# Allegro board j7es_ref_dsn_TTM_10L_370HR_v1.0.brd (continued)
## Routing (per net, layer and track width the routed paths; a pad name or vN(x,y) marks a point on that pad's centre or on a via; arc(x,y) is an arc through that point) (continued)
N31196104: length 5.5
  TOP w0.203: R1031.1 181.47,57 180.74,57 180.59,57.14 C1053.1 179.07,57.14 178.69,56.76 177.55,56.76 177.31,56.99 U1008.16
N31196146: length 8.7
  TOP w0.203: C1069.1 v2(173.86,44.57) ; U1008.7 173.41,50.72 v2(173.23,50.54)
  BOTTOM w0.203: v2(173.23,50.54) 173.23,45.2 v2(173.86,44.57)
N31196169: length 10.1
  TOP w0.203: v2(171.44,43.92) 171.45,43.93 171.45,43.93 171.96,44.44 R1046.1 ; U1008.5 172.11,50.69 v2(171.89,50.47)
  BOTTOM w0.203: v2(171.89,50.47) 172.72,49.65 172.72,46.73 171.45,45.46 171.45,43.93 v2(171.44,43.92)
N31196187: length 10.3
  TOP w0.203: R1042.1 172.21,48.25 172.09,48.38 v2(172.09,48.88) 172.09,49.65 172.59,50.15 172.59,50.92 172.76,51.08 U1008.6 ; C1071.2 v2(170.94,44.44)
  BOTTOM w0.203: v2(170.94,44.44) 170.94,45.84 172.09,46.98 v2(172.09,48.88)
N31196205: length 10.4
  TOP w0.203: U1008.4 171.46,50.8 171.32,50.66 v2(171.32,49.9) ; R1040.1 168.02,45.84 v2(168.4,45.46) R1045.1
  BOTTOM w0.203: v2(171.32,49.9) 171.32,48.38 v2(168.4,45.46)
N31196259: length 4.4
  TOP w0.203: U1008.9 174.71,49.31 R1036.2 174.77,49.25 174.77,48.39 174.62,48.25 C1065.1
N31196266: length 1.5
  TOP w0.203: C1064.1 173.37,47.89 173.37,48.4 173.23,48.54 R1036.1
N31197066: length 9.1
  TOP w0.203: C1070.1 v2(175.58,44.57) ; U1008.8 v2(174.06,50.54)
  BOTTOM w0.203: v2(174.06,50.54) 174.06,46.08 v2(175.58,44.57)
N31197134: length 6.8
  TOP w0.203: U1008.3 v2(170.81,50.54) ; C1062.2 169.41,48.12 v2(169.41,49.14) R1037.2
  BOTTOM w0.203: v2(170.81,50.54) v2(169.41,49.14)
N31197473: length 3.5
  TOP w0.203: R1035.2 181.48,49.52 181.63,49.66 182.48,49.66 R1038.1 TP1012.1
N31206842: length 11.8
  TOP w0.305: 163.32,17.13 163.83,16.63 165.23,16.63 165.54,16.93 U1006.2 ; 163.32,17.13 Q1002.4 ; 163.32,17.13 163.32,18.91 165.23,20.82 165.72,20.82 166.19,21.29 U1006.6
N31206856: length 5.5
  TOP w0.305: U1006.1 164.89,19.28 165.16,19.55 C1029.1
N31206860: length 6
  TOP w0.305: U1006.7 165.54,23.78 166.01,24.25 168.02,24.25 169.04,23.23 C1029.2
N31206880: length 14.7
  BOTTOM w0.127: v2(157.23,21.96) 155.19,19.93 155.19,12.56 154.69,12.05 152.27,12.05 151.76,11.55 R1131.2
N31207095: length 2.1
  TOP w0.127: v2(151.76,9.13) 151.61,9.29 DS1000.2
  BOTTOM w0.127: v2(151.76,9.13) R1131.1
N31208453: length 2.7
  TOP w0.203: U1007.13 v2(190.63,99.43)
  BOTTOM w0.203: v2(190.63,99.43) 190.63,98.29 R1139.2
N31208462: length 2
  TOP w0.203: v2(191.39,98.54) 191.79,98.94 U1007.14
  BOTTOM w0.203: v2(191.39,98.54) 191.13,98.29 R1140.1
N31208471: length 2.9
  TOP w0.203: U1007.8 190.13,102.08 v2(189.48,102.73)
  BOTTOM w0.203: R1144.2 188.98,103.24 v2(189.48,102.73)
N31208480: length 1.8
  TOP w0.203: v2(190.12,103.24) 190.12,102.78 190.32,102.58 U1007.7
  BOTTOM w0.203: R1145.1 v2(190.12,103.24)
N31208503: length 13.8
  L2-SIGNAL w0.305: v2(188.21,105.02) 179.27,105.02 v2(178.09,103.84)
  BOTTOM w0.305: Q1008.4 v2(178.09,103.84) ; v2(188.21,105.02) 190.12,105.02
N31208524: length 7.6
  BOTTOM w0.305: R1140.2 R1139.1 189.41,96.64 189.1,96.94 189.1,97.78 186.73,100.15 Q1007.4
N31208551: length 15.6
  TOP w0.203: U1007.12 190.02,100.09 189.74,99.81 v2(189.74,99.3) 189.1,98.67 C1037.1 ; R1017.1 v2(193.29,93.84)
  L4-SIGNAL w0.203: v2(189.74,99.3) 191.13,97.91 191.13,96 v2(193.29,93.84)
  BOTTOM w0.203: v2(189.74,99.3) 186.18,102.86
  vias: v2(178.44,102.99) v2(178.44,102.22) v2(180.72,103.62) v2(180.72,102.86) v2(180.72,102.1) v2(181.61,103.62) v2(181.61,102.86) v2(181.61,102.1) v2(183.26,102.99) v2(183.26,102.1) v2(184.02,102.99) v2(184.02,102.1) v2(184.78,102.99) v2(184.78,102.1)
N31208672: length 3.8
  TOP w0.203: U1007.11 189.12,100.59 C1037.2 D1004.1
N31208960: length 1.4
  BOTTOM w0.508: C1204.1 R1152.1
N31209649: length 6.2
  TOP w0.203: R1017.2 R1018.1 C1033.2 195.2,97.78 193.78,99.2 U1007.18
N31209654: length 4.8
  TOP w0.203: U1007.17 193.28,98.94 194.18,98.03 C1033.1 R1022.1 R1018.2
N31222073: length 5.2
  TOP w0.203: U1007.23 194.89,102.08 195.2,102.39 v2(195.2,102.99) 195.96,103.75 C1047.2
  BOTTOM w0.203: v2(195.2,102.99) 195.83,103.62 R1143.1
  BOTTOM w0.254: R1142.1 v2(195.2,102.99)
N31222132: length 1.4
  TOP w0.203: R1026.1 196.47,101.34 C1039.2
N31222198: length 3.5
  TOP w0.203: C1038.1 197.61,100.19 R1026.2 195.45,100.19 195.06,100.59 U1007.20
N31222241: length 3.5
  TOP w0.203: C1050.2 195.96,104.89 194.44,103.37 U1007.24
N31222246: length 2.5
  TOP w0.203: C1041.2 195.96,102.61 194.94,101.58 U1007.22
N31222265: length 3.6
  TOP w0.203: U1007.6 191.29,103.6 190.44,104.45 190.44,104.83 189.99,105.27 188.98,105.27
N31222285: length 3.4
  TOP w0.203: 191.01,105.27 192.02,105.27 191.44,104.69 191.44,104.08 191.79,103.73 U1007.5
N31222303: length 2.1
  TOP w0.203: v2(192.15,104.26) 192.28,104.12 U1007.4
  BOTTOM w0.203: 192.15,105.27 v2(192.15,104.26)
N31222717: length 1.1
  TOP w0.203: R1024.2 R1023.1
N31223527: length 2.4
  BOTTOM w0.305: v2(184.28,124.58) 184.66,124.2 R1138.1 R1136.1
N31223584: length 3.9
  TOP w0.305: C1026.1 v2(184.66,118.99) 184.91,118.99 184.97,119.04 U1005.5
  BOTTOM w0.305: R1137.1 v2(184.66,118.99)
N31223889: length 1.3
  TOP w0.305: 183.39,123.56 C1025.2
N31224124: length 3.4
  TOP w0.127: U1005.9 191.96,116.26 v2(192.41,115.81)
  BOTTOM w0.127: 193.55,116.58 R1132.1 v2(192.41,115.81)
N31225374: length 4.3
  TOP w0.127: R1010.2 175.26,127.75 175.26,129.89 174.85,130.29 U1001.6
N31225630: length 3.6
  TOP w0.305: U1005.11 v2(193.25,118.39)
  BOTTOM w0.305: R1135.2 192.06,118.39 v2(193.25,118.39)
N31225660: length 4.5
  TOP w0.305: RJ1001.2 R1016.1 184.15,117.46 184.15,117.85 184.7,118.39 U1005.6
N31226612: length 6.8
  TOP w0.127: v2(184.72,117.53) 184.94,117.74 U1005.7
  TOP w0.305: U1005.4 v2(184.4,119.69) 183.95,119.24 C1027.2
  BOTTOM w0.127: v2(184.4,119.69) 184.02,119.31 184.02,118.23 v2(184.72,117.53)
N31313642: length 3.4
  TOP w0.127: U1001.8 176.02,132.2 176.28,131.94 176.28,131.56 176.91,130.93 R1007.2
N31313645: length 4.6
  TOP w0.127: R1008.2 177.93,130.67 176.66,131.94 176.66,132.45 176.41,132.7 U1001.9
N31555915: length 2.3
  BOTTOM w0.305: C1199.1 R1136.2 R1138.2
N33657189: length 9.9
  TOP w0.508: R2027.2 v2(27.56,45.07) 27.81,45.33 C2035.2 R2032.2 ; R2025.2 v2(27.56,39.87)
  BOTTOM w0.508: v2(27.56,39.87) v2(27.56,45.07)
N33657272: length 2.5
  TOP w0.112: L2006.1 32.35,43.11 31.85,42.61 31.29,42.61 C2030.2
N33657370: length 2.4
  TOP w0.112: L2006.2 32.32,41.71 31.78,42.26 31.22,42.26 C2029.2
N33657483: length 6.1
  TOP w0.127: Y2000.3 46.18,48.58 v2(46.1,48.5) 46.1,46.47 47.24,45.33 U2011.5
  BOTTOM w0.127: C2127.1 v2(46.1,48.5)
N33657512: length 3.6
  TOP w0.127: U2011.4 47.74,45.87 v2(48.09,46.22) 48.09,46.26 48.06,46.29 Y2000.1
  BOTTOM w0.127: C2126.1 48.13,46.26 v2(48.09,46.22)
N33657557: length 2.8
  TOP w0.127: v2(49.66,46.22) 48.75,45.31 U2011.2
  BOTTOM w0.127: R2115.2 v2(49.66,46.22)
N33658409: length 3.4
  TOP w0.127: 33.66,35.17 v2(33.66,33.77)
  BOTTOM w0.127: R2106.2 R2107.1 v2(33.66,33.77)
N33658469: length 3.4
  TOP w0.127: 33.66,29.58 v2(33.66,30.98)
  BOTTOM w0.127: R2099.2 R2100.2 v2(33.66,30.98)
N33658487: length 3
  TOP w0.127: 34.92,35.17 v2(34.92,33.77)
  BOTTOM w0.127: R2108.2 v2(34.92,33.77) R2105.2
N33658532: length 4
  TOP w0.127: U2007.14 v2(41.27,30.98)
  BOTTOM w0.127: v2(41.27,30.98) 41.66,31.36 R2102.2 R2103.2
N33658660: length 2.4
  TOP w0.127: 34.92,29.58 v2(34.92,28.18)
  BOTTOM w0.127: v2(34.92,28.18) R2101.1
N33658666: length 4.2
  BOTTOM w0.127: R2098.2 R2104.1 C2116.1
N33658711: length 2.4
  TOP w0.127: 37.46,35.17 v2(37.46,36.57)
  BOTTOM w0.127: v2(37.46,36.57) R2109.2
N33658728: length 2.4
  TOP w0.127: U2007.1 v2(41.27,36.57)
  BOTTOM w0.127: v2(41.27,36.57) R2110.2
N289339640: length 2.9
  TOP w0.305: 183.26,120.77 C1025.1 183.9,120.77 184.32,120.35 U1005.3

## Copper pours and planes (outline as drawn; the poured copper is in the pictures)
DGND on TOP: 70.61,105.02 70.61,103.37 69.72,102.48 65.53,102.48 65.53,104 68.07,104 69.09,105.02
DGND on TOP: 163.07,66.41 163.07,51.17 190.12,51.17 191.64,52.69 191.64,66.41 177.42,66.41 176.97,66.86 176.97,67.24 177.04,67.3 177.04,67.81 176.15,68.7 171.96,68.7 171.96,67.05 171.32,66.41 ; 1 cut-out
DGND on TOP: 123.06,95.75 125.6,95.75 125.6,99.05 123.06,99.05 123.06,99.56 119.89,99.56 119.89,95.24 123.06,95.24
DGND on TOP: 53.72,9.01 53.72,2.4 53.21,1.89 47.5,1.89 47.12,2.28 47.12,3.8 46.48,4.43 46.48,6.59 47.24,7.36 47.24,8.63 48.01,9.39 53.34,9.39
DGND on TOP: 178.82,47.23 178.44,47.61 177.67,47.61 177.29,47.23 169.16,47.23 168.91,46.98 168.91,46.47 169.55,45.84 169.8,45.84 169.8,45.33 170.05,45.07 175.9,45.07 176.91,44.06 181.74,44.06 181.74,46.47 180.97,47.23
DGND on TOP: 101.63,29.92 101.59,29.94 101.57,29.97 101.57,33.08 101.57,33.09 101.56,33.11 101.11,33.56 101.1,33.58 101.09,33.6 101.09,36.58 101.1,36.6 101.11,36.62 101.2,36.71 101.22,36.72 101.24,36.73 103.89,36.73 103.91,36.72 103.93,36.71 104.89,35.75 104.9,35.74 104.9,35.72 104.9,29.97 104.89,29.94 104.85,29.92
DGND on TOP: 37.08,9.01 37.08,2.4 36.58,1.89 30.86,1.89 30.48,2.28 30.48,3.8 29.84,4.43 29.84,6.59 30.61,7.36 30.61,8.63 31.37,9.39 36.7,9.39
DGND on TOP: 74.8,114.67 74.8,112.13 78.1,112.13 78.1,114.67 78.61,114.67 78.61,117.85 74.3,117.85 74.3,114.67
DGND on TOP: 78.1,98.16 78.1,100.7 74.8,100.7 74.8,98.16 74.3,98.16 74.3,94.99 78.61,94.99 78.61,98.16
DGND on TOP: 87,9.26 87,2.66 86.49,2.15 80.77,2.15 80.39,2.53 80.39,4.05 79.76,4.69 79.76,6.85 80.52,7.61 80.52,8.88 81.28,9.64 86.61,9.64
DGND on TOP: 70.36,9.13 70.36,2.53 69.85,2.02 64.13,2.02 63.75,2.4 63.75,3.93 63.12,4.56 63.12,6.72 63.88,7.48 63.88,8.75 64.64,9.51 69.98,9.51
DGND on TOP: 24.13,22.09 24.13,18.02 23.75,17.64 23.75,16.63 21.72,16.63 21.21,17.13 20.83,17.13 20.45,16.75 20.45,15.61 20.7,15.36 21.59,15.36 22.1,15.86 26.29,15.86 26.67,16.25 26.67,21.58 25.78,22.47 24.51,22.47
DGND on TOP: 132.72,91.56 134.37,91.56 135.25,90.67 135.25,86.48 133.73,86.48 133.73,89.02 132.72,90.03
DGND on TOP: 139.57,99.05 137.03,99.05 137.03,95.75 139.57,95.75 139.57,95.24 142.75,95.24 142.75,99.56 139.57,99.56
DGND on TOP: 202.69,152.26 202.69,1.39 0.63,1.39 0.63,152.26 ; 2 cut-outs
DGND on BOTTOM: 132.84,94.12 130.18,94.12 130.18,93.74 129.95,93.51 127.3,93.51 127.13,93.69 127.13,95.87 123.57,95.87 122.94,95.24 119.89,95.24 119.89,99.56 123.06,99.56 123.7,98.92 126.26,98.92 126.87,99.53 126.87,100.19 128.52,100.19 128.52,100.14 131.9,100.14 132.21,100.45 132.21,100.7 132.46,100.95 135,100.95 135.51,100.45 135.51,99.05 135.64,98.92 139.06,98.92 139.7,99.56 142.75,99.56 142.75,95.24 139.7,95.24 139.7,95.27 139.08,95.89 139.06,95.87 135.81,95.87 135.81,93.46 133.12,93.46 132.84,93.74
DGND on BOTTOM: 73.18,104.89 73.18,107.56 72.8,107.56 72.57,107.79 72.57,110.43 72.75,110.61 74.93,110.61 74.93,114.16 74.3,114.8 74.3,117.85 78.61,117.85 78.61,114.67 77.98,114.04 77.98,111.47 78.59,110.86 81.08,110.86 81.08,109.24 79.2,109.24 79.2,105.93 79.43,105.7 81.1,105.7 81.1,102.22 78.1,102.22 77.98,102.1 77.98,98.67 78.61,98.03 78.61,94.99 74.3,94.99 74.3,98.03 74.32,98.03 74.94,98.66 74.93,98.67 74.93,101.92 72.52,101.92 72.52,104.61 72.8,104.89
DGND on BOTTOM: 95,1.04 94.74,1.3 94.74,2.82 95.07,3.15 99.87,3.15 100.08,2.95 100.08,1.17 99.95,1.04
DGND on BOTTOM: 94.72,14.94 94.72,11.84 100.46,11.84 100.46,14.94
DGND on BOTTOM: 103.5,72 103.5,72.89 103.12,73.27 99.82,73.27 99.57,73.01 99.57,72.63 102.49,72.63 102.74,72.38 102.74,72 103,71.74 103.25,71.74
DGND on BOTTOM: 202.69,152.26 202.69,1.39 0.63,1.39 0.63,152.26 ; 2 cut-outs
DGND on BOTTOM: 124.87,16 126.59,16 126.96,15.63 126.96,13.59 127.22,13.33 127.22,9.78 126.58,9.14 124.93,9.14 124.42,9.65 124.42,15.56
DGND on L2-SIGNAL: 202.69,152.26 202.69,1.39 0.63,1.39 0.63,152.26 ; 2 cut-outs
DGND on L3-GND, L8-GND: 202.69,152.26 202.69,1.39 0.63,1.39 0.63,152.26
DGND on L4-SIGNAL: 202.69,152.26 202.69,1.39 0.63,1.39 0.63,152.26 ; 1 cut-out
DGND on L5-PWR/GND: 110.24,75.81 134.24,75.81 137.8,72.25 137.8,59.93 133.22,55.36 109.86,55.36 106.11,59.11 106.11,60.06 107.31,61.27 107.31,62.73 106.55,63.49 106.55,64.89 105.92,65.52 105.92,71.49
DGND on L7-SIGNAL: 202.69,152.26 202.69,1.39 0.63,1.39 0.63,152.26 ; 1 cut-out
DGND on L9-SIGNAL: 202.69,152.26 202.69,1.39 0.63,1.39 0.63,152.26 ; 3 cut-outs
V3V3_DP0 on TOP: 128.54,15.19 129.86,15.19 129.86,11.99 128.54,11.99
V3V3_DP0 on BOTTOM: 129.38,15.62 129.38,12.06 129.25,11.94 127.98,11.94 127.73,12.19 127.73,13.84 127.6,13.97 127.6,15.62 127.73,15.75 129.25,15.75
VBAT on TOP: 155.57,13.96 162.94,13.96 163.96,12.94 163.96,6.72 162.94,5.7 154.56,5.7 153.29,6.97 153.29,11.67
VBAT_A on TOP: 162.43,43.8 162.43,37.45 160.53,35.55 154.31,35.55 153.03,36.82 153.03,40.38 156.46,43.8
VBAT_A on L5-PWR/GND: 189.99,34.66 158.24,34.66 156.72,36.18 156.72,40.76 159.26,43.3 186.82,43.3 190.88,39.23 190.88,35.55
VBAT_F on TOP: 171.2,73.65 171.2,67.17 162.94,67.17 162.81,67.3 162.81,72.63 163.83,73.65
VBAT_F on TOP: 185.04,42.53 185.04,42.15 188.98,38.22 188.98,34.41 186.82,32.25 186.82,5.07 181.36,5.07 181.36,10.02 176.4,14.98 176.4,27.04 172.59,30.85 165.61,30.85 162.81,33.64 162.81,48.25 163.96,49.39 166.12,49.39 166.62,48.88 166.62,44.57 168.66,42.53
VBAT_PM on TOP: 162.69,18.4 163.7,17.39 165.48,17.39 166.5,18.4 169.04,18.4 169.04,15.86 167.77,14.59 155.32,14.59 153.42,12.69 149.22,12.69 148.59,13.32 148.59,18.4
VBAT_PM on BOTTOM: 154.43,17.01 148.72,17.01 148.72,31.74 149.86,32.88 191.13,32.88 197.23,38.98 197.23,66.66 196.98,66.92 192.91,66.92 191.9,65.9 191.9,48 185.93,42.03 149.22,42.03 143.89,36.69 143.89,16.37 147.7,12.56 154.18,12.56 154.43,12.82
VBAT_SYS on TOP: 175.51,98.41 175.51,94.99 182.25,88.25 185.55,88.25 186.82,86.98 186.82,83.81 186.88,83.75 186.88,82.92 192.91,82.92 195.07,85.08 195.07,91.94 193.04,93.97 193.04,99.3 192.53,99.81 192.15,99.81 192.15,98.8 190.75,97.4 190.75,96 190.12,95.37 188.85,95.37 185.8,98.41 185.8,99.18 185.42,99.56 183.39,99.56 182.25,98.41
VBAT_SYS on BOTTOM: 183.01,99.43 186.31,99.43 188.47,97.27 188.47,96.38 188.72,96.13 191.26,96.13 191.64,96.51 191.64,98.92 196.09,98.92 196.98,99.81 196.98,100.7 195.96,101.72 195.96,102.48 196.22,102.73 199.77,102.73 200.28,102.22 200.28,95.62 194.94,90.29 180.59,90.29 180.59,97.02
VBAT_SYS on BOTTOM: 187.71,86.48 193.04,86.48 194.94,84.57 194.94,80.51 194.06,79.62 187.58,79.62 186.56,80.63 186.56,85.33
VBUS_USBC_CONN on TOP: 173.1,133.47 172.09,133.47 172.09,133.59 171.32,133.59 170.24,134.67 170.24,141.21 172.59,141.21 172.59,135.88 173.1,135.37
VBUS_USBC_CONN on L2-SIGNAL: 186.56,145.28 186.56,138.42 178.31,130.16 147.19,130.16 146.94,130.42 146.94,135.12 157.73,145.91 185.93,145.91
VCC_12V0 on TOP: 97.28,31.14 97.28,36.91 97.49,37.11 100.33,37.11 100.71,36.73 100.71,33.27 101.12,32.87 101.12,30.94 101.04,30.86 99.57,30.86 99.29,31.14
VCC_12V_DSI0 on TOP: 100.54,26.83 100.54,25.07 99.98,24.51 99.98,23.53 102.31,21.19 102.31,4.55 101.17,3.41 96.77,3.41 95.13,5.05 95.13,20.18 96.77,21.82 96.77,24.93 97.26,25.42 97.26,27.16 97.35,27.25 100.12,27.25
VCC_12V_DSI0 on BOTTOM: 96.01,8.03 101.35,8.03 102.62,6.76 106.68,6.76 106.93,6.5 106.93,4.34 106.35,3.76 96.34,3.76 95.76,4.34 95.76,7.77
VCCA_3V3 on TOP: 153.8,108.57 157.73,104.64 157.73,97.91 153.54,93.72 135.64,93.72 135.25,94.1 135.25,100.45 133.1,102.61 133.1,107.69 133.99,108.57
VCCA_3V3 on TOP: 123.95,99.43 127.51,99.43 127.63,99.56 127.63,99.81 126.62,99.81 125.73,100.7 123.95,100.7
VCCA_3V3 on TOP: 138.68,95.37 135.13,95.37 135,95.24 135,94.99 136.02,94.99 136.91,94.1 138.68,94.1
VCCA_3V3 on TOP: 78.49,99.05 78.49,102.61 78.61,102.73 78.87,102.73 78.87,101.72 79.76,100.83 79.76,99.05
VCCA_3V3 on TOP: 71.5,106.29 72.85,106.29 72.85,106.8 69.22,106.8 69.22,105.78 70.99,105.78
VCCA_3V3 on TOP: 74.42,99.05 74.42,102.61 74.3,102.73 74.04,102.73 74.04,101.72 73.15,100.83 73.15,99.05
VCCA_3V3 on TOP: 74.42,113.78 74.42,110.23 74.3,110.1 74.04,110.1 74.04,111.11 73.15,112 73.15,113.78
VCCA_3V3 on TOP: 138.68,99.43 135.13,99.43 135,99.56 135,99.81 136.02,99.81 136.91,100.7 138.68,100.7
VCCA_3V3 on TOP: 123.95,95.37 127.51,95.37 127.63,95.24 127.63,94.99 126.62,94.99 125.73,94.1 123.95,94.1
VCCA_3V3 on TOP: 131.24,93.79 130.94,93.79 130.94,90.16 131.95,90.16 131.95,91.68 131.32,92.32 131.32,93.72
VCCA_3V3 on TOP: 78.49,113.78 78.49,110.23 78.61,110.1 78.87,110.1 78.87,111.11 79.76,112 79.76,113.78
VCCA_3V3 on BOTTOM: 128.4,101.32 128.43,101.34 129.01,101.34 129.03,101.34 129.05,101.35 129.41,101.72 129.44,101.73 129.46,101.73 129.95,102.07 129.53,102.48 129.5,102.48 129.43,102.54 129.42,102.56 129.41,102.58 129.41,103.44 129.43,103.48 129.46,103.49 129.61,103.49 129.67,103.48 129.72,103.48 131.03,103.48 131.08,103.48 131.14,103.49 132.06,103.49 132.08,103.49 132.09,103.48 132.32,103.26 132.34,103.24 132.36,103.24 133.46,103.24 133.48,103.24 133.49,103.23 133.57,103.15 133.58,103.13 133.58,103.1 133.55,103 133.53,102.98 133.52,102.98 133.24,102.5 133.72,102.24 133.74,102.25 133.76,102.24 133.84,102.19 133.85,102.17 133.86,102.15 133.86,101.39 133.84,101.35 133.81,101.34 132.32,101.34 132.3,101.33 132.29,101.32 131.84,100.87 131.83,100.86 131.83,100.84 131.83,100.63 131.82,100.61 131.81,100.59 131.76,100.54 131.74,100.53 131.72,100.52 128.96,100.52 128.92,100.54 128.91,100.57 128.44,100.57 128.4,100.59 128.38,100.63 128.38,101.24
VCCA_3V3 on BOTTOM: 78.71,113.81 80.24,113.81 80.24,119.12 70.48,119.12 70.1,118.73 70.1,116.58 72.77,113.91 74.68,113.91 74.68,111.11 74.55,110.99 72.64,110.99 72.39,110.73 72.39,107.69 72.77,107.3 72.77,105.65 72.14,105.02 72.14,101.72 74.42,101.72 74.8,101.34 74.8,98.92 74.42,98.54 66.42,98.54 65.15,99.81 65.28,99.94 65.28,102.99 64.01,102.99 63.88,102.86 63.88,102.99 61.59,102.99 60.2,104.38 60.2,107.05 61.47,108.32 66.17,108.32 66.67,108.83 66.67,113.78 64.52,115.94 64.52,122.67 88.14,122.67 90.2,120.61 90.2,111.93 90.17,111.93 90.17,106.42 87.5,103.75 87.5,100.27 85.83,98.59 78.71,98.59
VCCA_3V3 on L5-PWR/GND: 157.48,97.65 157.48,103.11 155.32,105.27 152.4,105.27 150.11,107.56 128.02,107.56 123.06,102.61 123.06,92.57 125.86,89.78 135,89.78 141.35,96.13 155.96,96.13
VCCA_3V3 on L6-PWR/GND: 85.14,118.79 157.35,118.79 160.53,115.61 160.53,101.97 157.35,98.8 149.33,98.8 149.33,105.55 149.35,105.58 149.35,106.16 148.34,107.18 114.55,107.18 110.97,103.6 91.16,103.6 90.3,102.73 90.3,98.92 73.28,98.92 72.45,99.75 72.45,105.34 69.85,107.94 69.85,113.15 71.12,114.42 79.38,114.42 79.88,113.91 79.88,109.08 80.26,108.7 82.42,108.7 82.8,109.08 82.8,116.45
VCCA_3V3 on L7-SIGNAL: 63.75,118.73 63.75,98.08 88.37,98.08 88.37,98.16 89.28,99.08 89.28,107.91 88.37,108.83 88.37,109.72 89.51,110.86 89.51,118.73
VDD1_LPDDR4_1V8 on BOTTOM: 121.82,55.87 119.63,58.06 119.63,75.15 121.44,76.95 121.44,84.95 118.62,87.77 118.62,89.14 117.47,90.29 115.95,90.29 114.55,91.68 114.55,105.27 116.71,107.43 128.02,107.43 129.16,106.29 129.16,101.84 128.91,101.59 128.4,101.59 127,102.99 119,102.99 117.47,101.46 117.47,93.46 119.13,91.81 124.21,91.81 131.06,84.95 131.06,79.87 135.76,75.17 135.76,57.54 134.09,55.87 ; 4 cut-outs
VDD1_LPDDR4_1V8 on L9-SIGNAL: 130.69,68.24 130.69,64.68 129.21,63.21 129.21,62.01 126.67,62.01 126.04,62.65 121.71,62.65 120.32,61.26 120.32,56.62 120.54,56.4 134.49,56.4 135.51,57.42 135.51,76.57 121.5,76.57 120.58,75.65 120.58,71.24 121.68,70.14 127.05,70.14 128.96,68.24 ; 1 cut-out
VDD18_DSI on TOP: 116.97,33.55 116.97,35.47 116.5,35.93 112.3,35.93 111.27,34.91 111.27,33.95 111.67,33.55
VDD18_DSI on L2-SIGNAL: 115.32,35.93 117.35,33.9 117.35,17.52 114.68,14.85 104.27,14.85 103.63,15.48 103.63,16.37 104.65,17.39 112.52,17.39 114.81,19.67 114.81,28.95 114.17,29.58 112.78,29.58 112.27,29.07 110.87,29.07 110.49,29.45 110.49,34.15 112.27,35.93
VDD_CORE_0V8 on TOP: 77.23,74.56 76.7,75.09 74.9,75.09 73.28,76.71 73.28,81.14 59.44,94.99 59.44,114.8 64.52,119.88 86.23,119.88 97.54,108.57 97.54,97.53 98.68,96.38 103.63,96.38 104.14,95.87 104.14,93.97 103.25,93.08 101.73,93.08 101.41,92.76 101.41,91.49 99.69,89.78 99.69,84.06 99.39,83.76 87,83.76 86.55,83.31 86.55,74.35 87.72,73.19 94.91,73.19 96.52,74.79 97.03,74.79 98.77,73.05 98.84,73.05 98.93,73.14 98.93,73.4 97.92,74.41 97.92,74.67 98.17,74.92 98.81,74.92 98.81,75.43 98.93,75.55 99.57,75.55 99.57,73.14 100.08,72.63 100.08,70.91 100.84,70.91 100.84,67.08 94.81,67.08 94.81,72.8 87.11,72.8 85.47,71.16 80.62,71.16 80.62,73.78 80.52,73.78 80.26,74.03 80.26,74.43 80.14,74.56
VDD_CORE_0V8 on BOTTOM: 71.12,120.34 71.13,120.37 71.17,120.39 81.74,120.39 81.77,120.37 81.79,120.34 81.79,114.85 81.77,114.81 81.74,114.8 79.93,114.8 79.9,114.81 79.88,114.85 79.88,117.7 79.88,117.72 79.87,117.73 79.39,118.21 79.37,118.22 79.35,118.23 73.55,118.23 73.53,118.22 73.52,118.21 73.04,117.73 73.03,117.72 73.03,117.7 73.03,114.85 73.01,114.81 72.97,114.8 71.17,114.8 71.13,114.81 71.12,114.85
VDD_CORE_0V8 on BOTTOM: 81.79,98.03 81.79,92.45 71.12,92.45 71.12,98.03 73.03,98.03 73.03,95.11 73.53,94.6 79.38,94.6 79.88,95.11 79.88,98.03
VDD_CORE_0V8 on BOTTOM: 93.6,96 94.11,96 94.23,96.13 94.23,97.78 94.11,97.91 93.98,97.91 93.97,97.89 93.71,97.89 93.68,97.93 92.2,97.93 92.2,96.64 92.46,96.38 93.22,96.38
VDD_CORE_0V8 on L2-SIGNAL: 103.76,72.38 107.08,72.38 107.08,65.24 97.16,65.24 96.49,65.9 94.36,65.9 94.11,66.16 94.11,70.6 93.6,71.11 84.45,71.11 83.69,71.87 80.39,71.87 75.62,76.65 75.62,79.31 60.71,94.22 60.71,118.99 88.01,118.99 99.69,107.3 99.69,72.76 100.84,71.62 100.84,68.7 102.87,68.7 103.76,69.59
VDD_CORE_0V8 on L4-SIGNAL: 87.25,91.46 87.25,93.33 83.95,96.64 66.8,96.64 65.28,95.11 65.28,92.7 66.52,91.46
VDD_CORE_0V8 on L6-PWR/GND: 90.04,80.25 75.95,80.25 75.95,82.03 73.28,84.7 73.28,98.67 90.04,98.67
VDD_CORE_0V8 on L9-SIGNAL: 94.11,42.79 95.38,41.52 107.7,41.52 108.2,42.03 108.2,42.92 106.81,44.31 106.43,44.31 100.2,50.54 100.2,59.3 99.82,59.68 99.82,69.2 99.95,69.33 99.95,72.38 100.71,73.14 100.71,76.06 99.06,77.71 94.23,77.71 93.47,76.95 93.47,74.67 93.85,74.28 94.36,74.28 94.87,74.79 95.12,74.79 95.25,74.67 95.25,73.52 93.47,71.74 93.47,66.92 95.12,65.27 95.12,64.12 95.88,63.36 95.88,58.92 96.27,58.54 96.27,51.42 94.11,49.27
VDD_CORE_0V8_REG_SW1 on TOP: 73.86,110.78 73.86,110.1 73.03,110.1 73.03,110.23 71.37,111.88 71.37,114.16 72.52,114.16 72.52,112.13
VDD_CORE_0V8_REG_SW2 on TOP: 79.04,110.78 79.04,110.1 79.88,110.1 79.88,110.23 81.53,111.88 81.53,114.16 80.39,114.16 80.39,112.13
VDD_CORE_0V8_REG_SW3 on TOP: 73.86,102.05 73.86,102.73 73.03,102.73 73.03,102.61 71.37,100.95 71.37,98.67 72.52,98.67 72.52,100.7
VDD_CORE_0V8_REG_SW4 on TOP: 79.04,102.05 79.04,102.73 79.88,102.73 79.88,102.61 81.53,100.95 81.53,98.67 80.39,98.67 80.39,100.7
VDD_CORE_RAM_0V85 on BOTTOM: 75.44,79.39 75.44,78.88 75.4,78.84 72.01,78.84 72.01,77.1 77.47,77.1 77.47,80 76.05,80
VDD_CORE_RAM_0V85 on L6-PWR/GND: 98.87,67.7 97.71,68.86 97.71,71.41 97.64,71.49 84.84,71.49 82.03,74.3 78.48,74.3 76.71,76.06 76.71,79.2 77.47,79.96 90.57,79.96 90.75,79.77 90.75,75.1 92.46,73.4 94.87,73.4 94.87,75.43 95.38,75.43 95.72,75.09 100.5,75.09 101.19,74.39 101.19,73.15 102.04,73.15 102.04,67.7
VDD_CPU_AVS on TOP: 99.69,83.68 99.69,73.27 99.77,73.2 99.77,71.62 101.22,71.62 101.22,69.33 103.45,69.33 103.45,72.76 107.57,72.76 107.57,75.94 108.58,76.95 112.78,76.95 112.83,76.9 120.32,76.9 123.19,79.77 123.19,81.5 128.14,81.5 128.14,83.17 125.73,85.59 125.73,104.76 124.97,105.53 118.11,105.53 117.09,104.51 117.09,94.35 114.81,92.06 103,92.06 99.95,89.02 99.95,83.94
VDD_CPU_AVS on BOTTOM: 119.51,94.5 119.51,94.48 119.52,94.46 120,93.98 120.02,93.97 120.04,93.97 122.89,93.97 122.92,93.95 122.94,93.92 122.94,92.12 122.92,92.08 122.89,92.06 119.25,92.06 117.73,93.59 117.73,101.34 119.13,102.73 122.89,102.73 122.92,102.72 122.94,102.68 122.94,100.88 122.92,100.84 122.89,100.83 120.29,100.83 120.27,100.82 120.25,100.81 119.52,100.08 119.51,100.06 119.51,100.04
VDD_CPU_AVS on L2-SIGNAL: 102.74,68.95 103.5,69.71 103.5,72.38 103.76,72.63 107.01,72.63 110.92,76.55 120.65,76.55 123.57,79.47 128.02,79.47 128.02,100.19 126.24,101.97 125.98,101.97 123.19,104.76 118.24,104.76 116.84,103.37 116.84,99.2 106.15,88.51 99.95,88.51 99.96,88.5 99.96,72.65 100.99,71.62 100.99,68.95
VDD_CPU_AVS_REG_SW1 on TOP: 126.95,94.81 127.63,94.81 127.63,93.97 127.51,93.97 125.86,92.32 123.57,92.32 123.57,93.46 125.6,93.46
VDD_CPU_AVS_REG_SW2 on TOP: 126.95,99.99 127.63,99.99 127.63,100.83 127.51,100.83 125.86,102.48 123.57,102.48 123.57,101.34 125.6,101.34
VDD_CPU_RAM_0V85 on BOTTOM: 90.17,104.48 91.32,104.48 91.37,104.43 91.37,101.26 91.31,101.21 91.9,101.21 92.96,100.14 92.96,99.56 92.46,99.05 90.17,99.05
VDD_CPU_RAM_0V85 on L5-PWR/GND: 102.58,67.83 101.32,67.83 99.95,69.2 99.95,73.01 100.97,74.03 100.97,75.3 101.23,75.57 102.25,75.57 102.49,75.81 102.49,76.82 101.98,77.33 101.73,77.33 101.73,78.35 101.6,78.48 101.6,84.7 101.85,84.95 101.85,88.38 93.85,96.38 92.84,96.38 91.82,97.4 91.82,99.81 93.22,101.21 96.52,101.21 105.79,91.94 105.79,85.33 104.01,83.56 104.01,82.56 104.41,82.16 104.41,79.73 106.93,77.21 106.93,74.79 105.54,73.4 105.54,70.79
VDD_DDR_1V1 on TOP: 137.1,78.66 127.16,78.66 126.71,79.11 123.32,79.11 120.65,76.44 110.74,76.44 108.84,74.54 108.84,60.19 106.43,60.19 106.43,57.39 112.27,51.55 134.35,51.55 140.84,58.04 140.84,74.92 ; 15 cut-outs
VDD_DDR_1V1 on TOP: 141.08,104.89 141.1,104.89 141.11,104.88 142.73,103.26 142.74,103.24 142.75,103.22 142.75,101.13 142.73,101.1 142.7,101.08 139.5,101.08 139.46,101.1 139.45,101.13 139.45,102.84 139.44,102.86 139.43,102.87 138.95,103.35 138.94,103.36 138.92,103.37 136.7,103.37 136.67,103.38 136.65,103.42 136.65,104.84 136.67,104.88 136.7,104.89
VDD_DDR_1V1 on L2-SIGNAL: outline of 101 points within 137.67,68.95 145.29,103.75
VDD_DDR_1V1 on L6-PWR/GND: 103.09,66.53 103.25,66.38 103.34,66.47 103.34,73.07 105.49,73.07 106.06,73.64 110.05,73.64 110.26,73.42 118.9,73.42 120.27,74.79 120.27,90.85 121.23,91.81 121.28,91.81 121.41,91.94 121.41,100.32 122.36,101.27 132.91,101.27 134.56,102.92 142.81,102.92 143.13,102.61 143.13,94.25 139.73,94.25 138.54,93.07 138.54,90.66 137.92,90.03 137.92,79.62 140.59,76.95 140.59,60.44 134.24,54.09 123.57,54.09 121.22,51.74 105.79,51.74 103.11,54.42 103.11,56.87 103.09,56.89
VDD_DDR_1V1 on L7-SIGNAL: 137.51,71.22 137.51,59.85 133.19,55.54 120.37,55.54 119.63,56.28 119.63,74.79 121.16,76.32 132.41,76.32
VDD_DDR_1V1_REG_SW on TOP: 135.69,99.99 135,99.99 135,100.83 135.13,100.83 136.78,102.48 139.06,102.48 139.06,101.34 137.03,101.34
VDD_IO_1V8 on TOP: 117.47,34.82 117.47,33.55 120.65,33.55 120.65,34.82
VDD_IO_1V8 on L2-SIGNAL: 116.4,99.37 105.92,88.89 101.98,88.89 101.73,89.14 101.73,98.67 118.36,115.31 155.96,115.31 162.43,108.83 162.43,84.32 151.76,73.65 151.76,18.15 146.18,12.56 123.32,12.56 117.98,17.9 117.98,34.03 119.38,35.42 120.4,35.42 125.48,30.34 125.48,25.9 126.62,24.75 139.19,24.75 145.92,31.49 145.92,102.1 143.89,104.13 124.33,104.13 123.32,105.15 117.98,105.15 116.4,103.56
VDD_IO_1V8 on L5-PWR/GND: 80.39,107.81 99.31,107.81 99.38,107.75 102.43,107.75 110.62,99.56 110.62,95.75 108.84,93.97 104.52,93.97 96.9,101.59 81.53,101.59 80.39,102.73
VDD_IO_1V8 on L6-PWR/GND: 105.16,75.94 104.37,76.72 104.37,77.82 106.55,80 106.55,87.14 101.96,87.14 101.04,88.05 101.04,92.24 101.09,92.24 101.09,103.11 111.25,103.11 111.25,94.22 111.63,93.84 114.73,93.84 116.33,92.24 116.33,75.94
VDD_IO_3V3 on TOP: outline of 82 points within 98.55,96.64 117.47,117.97
VDD_IO_3V3 on TOP: 150.88,108.07 150.88,109.21 151.51,109.84 155.83,109.84 156.08,109.59 156.97,109.59 156.97,108.07
VDD_IO_3V3 on BOTTOM: 97.92,15.9 97.92,18.19 95.63,18.19 95.63,15.9
VDD_IO_3V3 on L5-PWR/GND: 202.69,152.26 202.69,1.39 0.63,1.39 0.63,152.26 ; 1 cut-out
VDD_IO_3V3 on L6-PWR/GND: 100.61,92.65 100.61,87.37 101.37,86.6 106.68,86.6 106.68,84.06 106.3,83.68 106.3,80.13 104.19,78.02 104.19,74.77 105.66,74.77 105.66,73.54 105.39,73.27 101.51,73.27 101.51,74.37 100.71,75.17 96.52,75.17 96.01,75.68 94.49,75.68 94.49,73.65 92.58,73.65 91.19,75.05 90.75,75.56 90.75,80.47 90.35,80.87 90.35,90.34 90.36,90.35 90.36,102.42 90.93,102.99 100.46,102.99 100.69,102.76 100.69,92.73
VDD_MCU_0V85 on TOP: 85.85,42.92 87,41.77 88.52,41.77 88.9,42.15 88.9,45.96 90.81,47.87 90.81,49.65 90.42,50.03 90.04,50.03 89.79,49.77 89.41,49.77 89.41,55.36 89.28,55.49 87.5,55.49 87.5,49.9 87.38,49.77 86.36,49.77 85.85,49.27
VDD_MCU_0V85 on TOP: 142.6,93.46 142.65,93.43 142.64,93.38 142.59,93.27 142.57,93.16 142.57,91.87 142.61,91.7 142.74,91.55 142.75,91.53 142.75,91.1 142.73,91.06 142.7,91.05 140.86,91.05 140.84,91.04 140.83,91.03 139.71,89.92 139.7,89.91 139.67,89.91 139.53,90.09 139.31,90.16 136.92,90.16 136.88,90.18 136.87,90.22 136.87,91.38 136.88,91.41 136.92,91.43 138.92,91.43 138.94,91.43 138.95,91.44 139.69,92.18 139.7,92.19 139.7,92.21 139.7,93.41 139.71,93.45 139.75,93.46
VDD_MCU_0V85 on L4-SIGNAL: 95.63,67.17 94.11,67.17 92.46,65.52 92.46,51.55 89.92,49.01 86.49,49.01 85.98,49.52 85.98,55.87 89.28,59.17 89.28,66.66 90.81,68.19 90.93,68.19 90.93,70.73 91.44,71.24 94.11,71.24 94.23,71.36 95.63,71.36
VDD_MCU_0V85 on L6-PWR/GND: 85.75,57.75 85.74,57.72 85.74,59.19 93.73,67.17 93.73,67.55 93.22,68.06 93.22,69.74 94.49,71.01 95.17,71.01 95.17,70.58 95.43,70.58 95.68,70.83 96.75,70.83 96.9,70.68 96.9,68.67 97.59,67.99 97.59,64.94 97.61,64.91 97.59,64.89 97.59,48.33 100.33,45.58 102.49,45.58 103.89,46.98 103.89,49.14 105.66,50.92 121.41,50.92 123.83,53.33 134.75,53.33 141.73,60.31 141.73,77.08 138.68,80.13 138.68,89.7 140.13,91.15 140.13,91.61 139.29,92.45 139.29,93.33 139.8,93.84 145.57,93.84 148.87,90.54 151.64,90.54 153.67,88.51 153.67,61.71 136.78,44.82 122.05,44.82 120.9,43.68 120.9,38.72 119.89,37.71 92.33,37.71 85.75,44.29
VDD_MCU_0V85_REG_SW on TOP: 135.69,94.81 135,94.81 135,93.97 135.13,93.97 136.78,92.32 139.06,92.32 139.06,93.46 137.03,93.46
VDD_MCU_RAM_0V85 on L5-PWR/GND: 99.69,73.27 99.69,64.76 95.5,60.57 95.5,51.55 90.81,46.85 88.39,46.85 88.01,47.23 88.01,49.01 90.3,51.3 90.3,55.87 93.34,58.92 93.34,63.36 91.82,64.89 91.82,72.13 93.09,73.4 99.57,73.4
VDD_MCUIO_1V8 on L4-SIGNAL: 94.87,66.92 95.38,66.41 95.38,65.65 94.78,65.05 94.78,64.72 94.74,64.68 94.74,58.09 95.98,56.85 95.98,49.23 94.49,47.74 94.49,46.73 91.31,43.55 91.31,41.77 92.84,40.25 140.84,40.25 144.02,43.42 144.02,89.14 140.08,93.08 140.08,99.18 136.27,102.99 130.94,102.99 130.68,102.73 130.68,102.1 130.3,101.72 128.78,101.72 128.27,102.22 128.27,107.43 129.54,108.7 145.03,108.7 146.81,106.92 146.81,99.18 153.23,92.76 153.23,42.85 145.8,35.42 74.42,35.42 68.26,41.58 68.26,47.42 69.09,48.25 75.44,48.25 77.6,50.41 81.79,50.41 85.98,46.22 89.53,46.22 90.17,46.85 90.17,48.63 92.84,51.3 92.84,65.52 94.23,66.92
VDD_MCUIO_3V3 on BOTTOM: 59.94,96.76 59.31,97.4 59.31,100.32 61.21,100.32 62.61,101.72 63.5,101.72 63.5,100.45 62.1,99.05 62.1,96.76
VDD_MCUIO_3V3 on L4-SIGNAL: 77.34,103.24 77.34,99.3 76.33,98.29 57.66,98.29 57.28,98.67 57.28,101.59 59.31,103.62 76.96,103.62
VDD_MCUIO_3V3 on L6-PWR/GND: 92.96,70.63 84.61,70.63 84.23,71.01 84.2,70.98 83.19,72 80.77,72 78.87,70.09 77.22,70.09 77.09,70.22 69.09,70.22 60.71,78.6 60.71,101.08 57.28,101.08 56.52,100.32 56.52,75.81 72.01,60.31 72.01,48.76 71.5,48.25 71.5,46.85 85.47,46.85 85.47,59.3 92.58,66.41 92.71,66.41 93.15,66.85 93.29,66.85 93.67,67.23 93.67,67.55 92.96,68.26
VDD_PHYIO_1V8 on TOP: 102.17,103.33 102.29,103.44 102.29,105.2 100.91,105.2 100.53,104.82 100.53,103.77 100.98,103.33
VDD_PHYIO_1V8 on TOP: 127.63,89.4 127.63,84.44 131.19,80.89 140.33,80.89 141.73,82.29 141.73,84.44 140.84,85.33 133.15,85.33 132.08,86.4 132.08,89.4
VDD_PHYIO_1V8 on L4-SIGNAL: 108.23,76.72 107.31,75.81 107.31,74.79 105.5,74.79 104.87,75.43 104.87,77.17 107.82,80.13 110.49,80.13 112.9,82.54 112.9,101.72 111.38,103.24 105.41,103.24 104.9,103.75 101.98,103.75 101.47,104.26 101.47,105.15 102.36,106.03 113.03,106.03 116.97,102.1 116.97,92.95 120.4,89.52 131.83,89.52 132.46,88.89 132.46,77.71 131.47,76.72
VDD_PHYIO_1V8 on L4-SIGNAL: 91.69,43.17 91.69,41.65 92.84,40.5 140.33,40.5 143.64,43.8 143.64,82.41 142.75,83.3 139.57,83.3 138.68,82.41 138.68,51.55 130.94,43.8 99.44,43.8 98.81,43.17
VDD_PHYIO_1V8_REG_SW on TOP: 129.67,92.06 129.67,93.84 130.68,93.84 130.68,91.38 129.92,90.62 129.92,90.41 127.63,90.41 127.63,91.68 129.29,91.68
VDD_RAM_0V85 on TOP: 68.45,110.1 65.46,110.1 65.46,105.65 68.45,105.65
VDD_RAM_0V85 on BOTTOM: 93.47,102.73 93.73,102.99 93.73,103.88 93.22,104.38 91.96,104.38 91.96,102.73
VDD_RAM_0V85 on L4-SIGNAL: 80.39,109.08 86.11,109.08 92.71,102.48 93.34,102.48 93.85,102.99 93.85,112.89 88.52,118.23 70.87,118.23 64.9,112.26 64.9,106.16 65.53,105.53 68.07,105.53 69.47,106.92 69.47,107.94 73.28,107.94 74.68,106.54 79.76,106.54 80.39,107.18
VDD_RAM_0V85 on L6-PWR/GND: 69.41,78.79 65.02,83.17 65.02,107.18 65.66,107.81 69.47,107.81 70.48,106.8 70.48,105.4 71.37,104.51 71.37,98.92 72.64,97.65 72.64,81.65 72.26,81.27 72.26,79.11 71.95,78.79
VDD_RAM_0V85_REG_SW on TOP: 71.12,108.07 72.9,108.07 72.9,106.87 70.61,106.87 69.67,107.81 69.47,107.81 69.47,110.1 70.74,110.1 70.74,108.45
VDD_SD_DV on L4-SIGNAL: 94.56,71.95 94.56,72.68 84.4,72.68 83.11,73.98 79.38,73.98 79.38,73.9 78.74,73.9 77.98,73.14 77.98,70.91 78.87,70.02 82.09,70.02 82.93,70.86 90.55,70.86 91.19,71.49 94.11,71.49
VDD_SD_DV on L6-PWR/GND: 61.09,116.32 64.26,119.5 78.61,119.5 82.55,115.56 82.55,109.46 82.04,108.96 80.64,108.96 80.26,109.34 80.26,113.91 79.5,114.67 69.6,114.67 64.64,109.72 64.64,82.41 73.41,73.65 77.72,73.65 77.72,73.52 78.87,72.38 78.87,70.47 69.47,70.47 61.09,78.86
VDDA_0P8_CSIRX on L4-SIGNAL: outline of 149 points within 95.12,47.61 97.79,66.03
VDDA_0P8_DP on L4-SIGNAL: 101.6,59.26 101.6,64.55 101.01,65.14 101.01,67.02 103.23,67.02 103.52,66.74 103.52,65.27 103.9,64.89 105.16,64.89 105.41,64.63 105.41,59.17 109.35,55.23 109.35,46.98 109.09,46.73 106.3,46.73 103.76,49.27 103.76,57.11
VDDA_0P8_DP_C on L4-SIGNAL: 100.85,65.86 100.85,64.8 101.35,64.3 101.35,59.17 103.5,57.01 103.5,49.01 106.04,46.47 109.22,46.47 109.47,46.73 110.36,46.73 110.62,46.47 110.62,44.57 110.24,44.19 102.11,44.19 99.95,46.34 99.95,57.9 99.19,58.66 99.19,66.21 99.39,66.41 100.3,66.41
VDDA_0P8_DSITX on L4-SIGNAL: 99.69,57.77 99.69,46.85 99.06,46.22 96.52,46.22 96.14,46.6 96.14,47.11 96.39,47.36 97.16,47.36 98.04,48.25 98.04,57.39 96.77,58.66 96.77,65.14 96.9,65.27 96.9,66.66 97.54,67.3 98.93,67.3 99.19,67.05 99.19,66.66 98.93,66.41 98.93,58.54
VDDA_0P8_PLL_DDR on TOP: 121.46,46.88 122.73,46.88 122.99,46.62 123.39,46.62 123.39,43.5 123.8,43.09 125.22,43.09 125.39,43.27 125.39,50.14 124.67,50.86 121.78,50.86 121.16,50.24 121.16,47.18
VDDA_0P8_PLL_DDR on L7-SIGNAL: 103.19,70.2 104.27,70.2 104.76,69.7 104.76,65.53 107.7,62.6 110.62,62.6 123.19,50.03 123.19,48.5 122.68,48 121.03,48 111.12,57.9 111.12,60.06 110.24,60.95 107,60.95 103.19,64.76
VDDA_0P8_PLL_MLB on TOP: 112.27,102.22 112.27,98.03 114.43,98.03 114.43,100.7 115.19,101.46 116.71,101.46 116.71,102.99 113.03,102.99
VDDA_0P8_PLL_MLB on L6-PWR/GND: 106.48,75.63 106.48,74.36 107.06,73.78 118.36,73.78 120.04,75.45 120.04,91.05 121.03,92.04 121.03,98.29 119.76,99.56 112.78,99.56 111.89,98.67 111.89,94.73 112.33,94.29 115.13,94.29 116.71,92.7 116.71,75.81 116.54,75.63
VDDA_0P8_SERDES on TOP: 90.6,98.21 91.53,98.21 91.69,98.05 91.69,94.99 91.95,94.73 91.95,92.27 91.82,92.14 89.97,92.14 89.53,92.57 89.53,97.14
VDDA_0P8_SERDES on L5-PWR/GND: 102.36,76.82 102.36,76.06 102.02,75.72 101.13,75.72 100.71,75.3 100.71,74.16 100.33,73.78 95.12,73.78 92.96,75.94 92.96,84.06 88.9,88.13 88.9,92.57 89.66,93.33 90.68,93.33 91.06,92.95 91.06,91.18 91.5,90.73 92.9,90.73 97.03,86.6 97.03,84.57 97.05,84.55 98.17,83.43 98.17,78.73 97.66,78.22 97.66,77.51 97.94,77.23 101.95,77.23
VDDA_0P8_SERDES_C on BOTTOM: 90.25,97.83 91.54,97.83 91.58,97.79 91.58,96.62 91.82,96.38 91.82,92.32 91.57,92.06 91.06,92.06 90.25,92.87
VDDA_0P8_SERDES_C on L5-PWR/GND: 94.04,95.87 92.2,95.87 91.31,94.99 91.31,91.43 91.78,90.97 93.22,90.97 96.31,87.87 96.31,86.18 98.42,84.06 98.42,78.6 97.92,78.09 97.92,77.46 101.47,77.46 101.47,77.46 101.6,77.59 101.6,84.57 101.41,84.76 101.41,88.51
VDDA_1P8_DP on L6-PWR/GND: 102.75,66.99 102.75,48.38 101.98,47.61 101.6,47.61 100.58,48.63 100.58,58.16 100.08,58.66 100.08,65.14 100.58,65.65 100.58,66.66 100.84,66.92 100.84,66.99
VDDA_1P8_DSITX on L6-PWR/GND: 100.2,57.9 99.82,58.28 99.82,65.27 100.2,65.65 100.2,66.77 99.92,67.05 99.06,67.05 98.55,66.54 98.55,48.38 100.46,46.47 101.85,46.47 102.11,46.73 102.11,47.36 101.47,47.36 100.2,48.63
VDDA_1P8_SERDES on TOP: 98.17,99.13 98.17,105.4 100.1,105.4 100.1,98.54 98.76,98.54
VDDA_1P8_SERDES on L4-SIGNAL: outline of 279 points within 97.28,77.08 103.25,100.45
VDDA_1P8_UFS on BOTTOM: 105.84,104.83 106.03,105.02 107.21,105.02 107.29,104.94 107.29,103.81 107.42,103.68 107.42,101.66 107.44,101.63 107.44,99.59 107.82,99.59 107.87,99.64 108.16,99.64 108.2,99.68 108.58,99.3 108.58,98.92 108.33,98.66 106.65,98.66 105.84,99.48
VDDHS11_DSI on TOP: 113.54,29.45 113.54,27.55 113.66,27.42 118.74,27.42 119.13,27.8 119.13,28.95 119,29.07 117.86,29.07 116.71,30.22 114.3,30.22
VDDHS11_DSI on L2-SIGNAL: 105.66,17.64 112.39,17.64 114.55,19.8 114.55,28.82 114.05,29.33 113.03,29.33 112.52,28.82 112.52,21.96 110.62,20.06 106.55,20.06 105.16,18.66 105.16,18.15
VDDP11_DSI on TOP: 117.98,25.9 120.27,25.9 121.03,26.66 121.03,28.18 119.63,28.18 119.63,27.17 119.51,27.04 117.98,27.04
VDDP11_DSI on L7-SIGNAL: 102.23,29.71 104.52,29.71 107.31,26.91 120.14,26.91 120.14,21.33 115.57,16.75 110.74,16.75 101.35,26.15 101.35,28.82
CS_P on TOP: 171.58,72.63 171.58,68.95 177.04,68.95 177.04,69.84 178.18,69.84 178.18,72.63
HDRV1_N on TOP: 168.27,73.9 168.27,86.22 168.53,86.48 175.26,86.48 175.26,72.89 171.58,72.89 171.58,73.9
HDRV2_N on TOP: 175.51,72.89 175.51,86.48 184.15,86.48 184.15,74.79 184.02,74.79 184.02,73.9 179.7,73.9 179.7,72.89
USB1_VBUS on TOP: 161.93,131.56 162.69,131.56 162.94,131.82 162.94,133.59 164.21,134.86 164.21,136.26 164.95,137 161.93,137 161.93,134.61 161.67,134.36 161.67,131.82
VCAM_9V0 on TOP: 60.83,5.83 62.61,5.83 62.86,6.09 62.86,6.59 61.85,7.61 61.85,8.75 61.59,9.01 60.83,9.01 60.58,8.75 60.58,6.09
VCAM_9V0 on TOP: 44.2,5.7 45.97,5.7 46.23,5.96 46.23,6.47 45.21,7.48 45.21,8.63 44.96,8.88 44.2,8.88 43.94,8.63 43.94,5.96
VCAM_9V0 on TOP: 27.56,5.7 29.34,5.7 29.59,5.96 29.59,6.47 28.57,7.48 28.57,8.63 28.32,8.88 27.56,8.88 27.3,8.63 27.3,5.96
VCAM_9V0 on TOP: 77.47,5.96 79.25,5.96 79.5,6.21 79.5,6.72 78.49,7.74 78.49,8.88 78.23,9.13 77.47,9.13 77.22,8.88 77.22,6.21
VDA_DLL_0V8 on TOP: 113.92,95.57 115.27,95.57 115.27,95.62 116.84,97.2 116.84,101.21 115.44,101.21 115.06,100.83 115.06,98.08 114.55,97.58 113.92,97.58
VDA_DLL_0V8 on L6-PWR/GND: 137.03,44.31 122.3,44.31 121.28,43.3 121.28,38.85 122.43,37.71 140.21,37.71 160.78,58.28 160.78,96.51 158.93,98.36 148.72,98.36 148.72,102.73 148.65,102.8 148.65,106.23 148.08,106.8 115.19,106.8 113.16,104.76 113.16,100.57 113.79,99.94 120.65,99.94 122.3,101.59 132.59,101.59 134.24,103.24 143,103.24 143.64,102.61 143.64,94.25 145.69,94.25 148.77,91.18 152.4,91.18 154.43,89.14 154.43,61.71
VDA_MCU_1V8 on TOP: 64.36,73.52 64.36,73.57 62.13,73.57 62.13,71.77 60.45,71.77 60.45,67.93 63.37,65.01 68.58,65.01 72.14,61.46 72.14,33.26 73.15,32.25 74.93,32.25 75.82,33.14 75.82,64.38 72.07,68.13 72.07,71.43 69.98,73.52
VDA_MCU_1V8 on BOTTOM: 60.32,70.65 64.36,70.65 64.8,70.22 69.72,70.22 70.61,71.11 70.61,72.13 69.34,73.4 66.04,73.4 65.86,73.57 62.1,73.57 62.1,71.9 60.32,71.9
VDA_MCU_1V8 on L2-SIGNAL: outline of 399 points within 61.72,63.62 96.52,74.03
VDA_MCU_1V8 on L4-SIGNAL: 162.94,101.72 162.94,39.36 154.69,31.1 74.42,31.1 73.41,32.12 73.41,34.28 74.17,35.04 146.43,35.04 153.8,42.41 153.8,92.83 147.32,99.3 147.32,107.05 145.29,109.08 129.29,109.08 127.89,107.69 127.89,101.97 128.52,101.34 130.56,101.34 130.94,101.72 130.94,102.48 131.32,102.86 132.84,102.86 133.22,102.48 133.22,98.8 132.33,97.91 125.86,97.91 124.46,99.3 124.46,111.62 126.87,114.04 150.62,114.04
VDA_PLL_1V8 on L4-SIGNAL: 96.2,67.85 96.43,67.62 103.63,67.62 103.63,65.65 104.14,65.14 105.28,65.14 105.66,65.52 105.66,70.98 104.52,72.13 103.63,72.13 95.88,79.87 95.88,83.68 94.49,85.08 94.49,93.84 88.52,99.81 87.88,99.81 81.41,106.29 80.39,106.29 79.63,105.53 79.63,101.59 87.88,93.33 87.88,87.24 89.15,85.97 89.15,80.51 91.5,78.16 91.5,72.86 95.61,72.86 96.2,72.27
VDA_PLL_1V8 on L7-SIGNAL: outline of 144 points within 92.71,70.86 97.03,76.7
VDA_USB_3V3 on L4-SIGNAL: 93.34,101.34 85.85,108.83 80.64,108.83 80.64,107.56 87.95,100.26 89.03,100.26 91.12,98.16 92.71,98.16 93.34,98.8
VPP_EFUSE_1V8 on BOTTOM: 115.57,86.98 116.97,86.98 117.86,87.87 117.86,89.65 117.47,90.03 112.14,90.03 110.36,88.25 110.36,84.95 103.89,78.48 103.5,78.48 103.38,78.35 103.38,77.71 103.12,77.46 102.74,77.46 102.23,77.97 101.73,77.97 101.6,77.84 101.6,76.7 102.11,76.19 103.38,76.19 104.9,77.71 106.3,77.71
VSYS_3V3 on TOP: 23.75,15.61 26.54,15.61 26.8,15.36 26.8,11.55 26.42,11.17 24.89,11.17 24.64,11.42 24.64,14.34 24.26,14.72 23.75,14.72
VSYS_3V3 on TOP: 158.37,110.86 158.37,108.32 159.13,107.56 159.13,98.8 159.51,98.41 164.21,98.41 164.85,97.78 164.85,97.02 165.86,97.02 165.99,97.14 171.2,97.14 174.5,100.45 174.5,105.65 175.51,105.65 178.94,109.08 188.09,109.08 188.09,112.38 186.31,114.16 161.67,114.16
VSYS_3V3 on BOTTOM: 175.9,106.42 170.56,106.42 170.18,106.8 170.18,107.94 171.96,109.72 175.26,109.72 176.15,108.83 176.15,106.67
VSYS_3V3 on L6-PWR/GND: 202.69,152.26 202.69,1.39 0.63,1.39 0.63,152.26 ; 2 cut-outs
VSYS_5V0 on TOP: 23.49,16.88 23.49,22.09 22.42,23.17 20.26,23.17 19.18,22.09 19.18,20.31 19.56,19.93 21.46,19.93 21.72,19.67 21.72,18.28 22.73,18.28 23.11,17.9 23.11,16.88
VSYS_5V0 on L5-PWR/GND: 29.97,20.44 36.7,13.71 121.16,13.71 179.58,72.13 179.58,95.62 182.5,98.54 194.18,98.54 194.18,92.57 184.78,83.17 184.78,65.52 163.96,44.69 163.96,44.44 163.83,44.31 159.64,44.31 155.26,39.93 155.26,32.95 130.81,8.5 22.35,8.5 18.29,12.56 18.29,29.58 23.49,34.79 38.35,34.79 39.12,34.03 39.12,31.36 37.85,30.09 31.75,30.09 29.97,28.31
VSYS_10V5 on TOP: 156.84,67.05 157.35,67.55 157.35,68.7 156.72,69.33 149.61,69.33 149.1,69.84 145.29,69.84 145.29,68.44 146.69,67.05
VSYS_16V0 on TOP: 179.96,67.3 179.96,73.65 190.63,73.65 191.52,72.76 191.52,67.3
VSYS_16V0 on TOP: 190.88,118.73 193.55,118.73 193.8,118.48 193.8,116.83 194.5,116.13 198.69,116.13 199.9,117.34 199.9,119.5 199.64,119.75 193.68,119.75 193.42,120 190.88,120
VSYS_16V0 on TOP: 154.18,59.93 160.15,59.93 160.78,60.57 160.78,63.24 160.66,63.36 157.23,63.36 156.72,62.85 156.72,61.58 156.46,61.33 154.18,61.33
VSYS_16V0 on BOTTOM: 184.28,67.68 184.28,70.86 184.53,71.11 191.39,71.11 191.64,70.86 191.64,67.68
VSYS_16V0 on L6-PWR/GND: 160.4,9.26 160.4,36.06 184.78,60.44 184.78,100.57 193.55,109.34 193.55,117.34 195.58,119.37 200.41,119.37 201.04,118.73 201.04,100.57 195.83,100.57 192.66,97.4 192.66,95.75 193.04,95.37 201.04,95.37 201.04,36.69 170.31,5.96 163.7,5.96
VSYS_16V0 on L7-SIGNAL: 155.7,53.33 179.83,53.33 192.79,66.28 192.79,70.73 190.37,73.14 166.5,73.14 153.92,60.57 153.92,55.11
VUSB_5V0 on TOP: 173.61,131.43 172.72,131.43 172.72,130.16 171.83,129.28 171.83,127.88 171.58,127.62 171.58,123.31 171.96,122.93 173.1,122.93 173.61,123.43
VUSB_5V0 on TOP: 189.48,123.05 189.48,129.28 197.48,129.28 197.48,126.48 191.9,126.48 191.52,126.1 191.52,123.05
VUSB_5V0 on L6-PWR/GND: 197.74,128.89 196.09,130.55 172.47,130.55 171.32,131.69 159.26,131.69 159.26,128.51 163.83,123.94 170.81,123.94 179.96,114.8 192.79,114.8 193.29,115.31 193.29,118.23 197.74,122.67
N28833063 on TOP: 78.1,2.02 78.61,2.53 78.61,3.93 79.38,4.69 79.38,4.82 78.99,5.2 77.22,5.2 76.58,4.56 76.58,2.28 76.83,2.02
N28833063 on BOTTOM: 85.6,5.45 85.72,5.32 85.72,5.07 84.33,3.67 84.33,2.02 76.83,2.02 76.58,2.28 76.58,4.31 76.83,4.56 84.33,4.56 85.22,5.45
N28833077 on BOTTOM: 78.74,13.32 78.74,9.13 77.22,9.13 77.22,6.59 84.33,6.59 84.96,5.96 85.6,5.96 85.72,6.09 85.72,6.34 84.33,7.74 84.33,9.13 80.14,9.13 80.14,13.71 80.39,13.96 80.39,14.21 80.26,14.34 79.76,14.34
N28833083 on BOTTOM: 80.9,13.96 81.28,13.58 81.28,10.28 82.55,10.28 82.55,10.91 84.07,10.91 84.2,11.04 84.2,11.55 84.07,11.67 82.55,11.67 82.55,13.71 81.91,14.34 81.03,14.34 80.9,14.21
N28846480 on BOTTOM: 64.26,13.83 64.64,13.45 64.64,10.15 65.91,10.15 65.91,10.78 67.44,10.78 67.56,10.91 67.56,11.42 67.44,11.55 65.91,11.55 65.91,13.58 65.28,14.21 64.39,14.21 64.26,14.09
N28846484 on BOTTOM: 62.1,13.2 62.1,9.01 60.58,9.01 60.58,6.47 67.69,6.47 68.33,5.83 68.96,5.83 69.09,5.96 69.09,6.21 67.69,7.61 67.69,9.01 63.5,9.01 63.5,13.58 63.75,13.83 63.75,14.09 63.63,14.21 63.12,14.21
N28846490 on TOP: 61.47,1.89 61.98,2.4 61.98,3.8 62.74,4.56 62.74,4.69 62.36,5.07 60.58,5.07 59.94,4.43 59.94,2.15 60.2,1.89
N28846490 on BOTTOM: 68.96,5.32 69.09,5.2 69.09,4.94 67.69,3.55 67.69,1.89 60.2,1.89 59.94,2.15 59.94,4.18 60.2,4.43 67.69,4.43 68.58,5.32
N28847093 on BOTTOM: 47.62,13.71 48.01,13.32 48.01,10.02 49.28,10.02 49.28,10.66 50.8,10.66 50.93,10.78 50.93,11.29 50.8,11.42 49.28,11.42 49.28,13.45 48.64,14.09 47.75,14.09 47.62,13.96
N28847097 on BOTTOM: 45.47,13.07 45.47,8.88 43.94,8.88 43.94,6.34 51.05,6.34 51.69,5.7 52.32,5.7 52.45,5.83 52.45,6.09 51.05,7.48 51.05,8.88 46.86,8.88 46.86,13.45 47.12,13.71 47.12,13.96 46.99,14.09 46.48,14.09
N28847103 on TOP: 44.83,1.77 45.34,2.28 45.34,3.67 46.1,4.43 46.1,4.56 45.72,4.94 43.94,4.94 43.31,4.31 43.31,2.02 43.56,1.77
N28847103 on BOTTOM: 52.32,5.2 52.45,5.07 52.45,4.82 51.05,3.42 51.05,1.77 43.56,1.77 43.31,2.02 43.31,4.05 43.56,4.31 51.05,4.31 51.94,5.2
N28847739 on BOTTOM: 30.99,13.71 31.37,13.32 31.37,10.02 32.64,10.02 32.64,10.66 34.16,10.66 34.29,10.78 34.29,11.29 34.16,11.42 32.64,11.42 32.64,13.45 32,14.09 31.11,14.09 30.99,13.96
N28847743 on BOTTOM: 28.83,13.07 28.83,8.88 27.3,8.88 27.3,6.34 34.42,6.34 35.05,5.7 35.69,5.7 35.81,5.83 35.81,6.09 34.42,7.48 34.42,8.88 30.23,8.88 30.23,13.45 30.48,13.71 30.48,13.96 30.35,14.09 29.84,14.09
N28847749 on TOP: 28.19,1.77 28.7,2.28 28.7,3.67 29.46,4.43 29.46,4.56 29.08,4.94 27.3,4.94 26.67,4.31 26.67,2.02 26.92,1.77
N28847749 on BOTTOM: 35.69,5.2 35.81,5.07 35.81,4.82 34.42,3.42 34.42,1.77 26.92,1.77 26.67,2.02 26.67,4.05 26.92,4.31 34.42,4.31 35.31,5.2
N30808408 on TOP: 23.24,15.48 23.24,14.47 22.48,13.71 22.48,11.29 24,11.29 24,14.09 23.62,14.47 23.62,14.59 23.49,14.72 23.49,15.48
N30812993 on TOP: 148.97,61.58 150.62,61.58 150.88,61.84 150.88,64.63 151.38,64.63 151.38,65.78 147.57,65.78 147.57,64.63 148.84,64.63 148.84,61.71
N31206880 on TOP: 156.97,18.79 156.97,20.06 155.7,21.33 155.7,23.99 155.77,24.06 155.77,27.1 158.75,30.09 172.47,30.09 175.64,26.91 175.64,15.48 170.56,15.48 170.31,15.74 170.31,23.36 168.78,24.88 165.61,24.88 165.1,24.37 165.1,21.45 162.43,18.79
N31207093 on BOTTOM: 153.16,18.66 153.16,28.18 153.03,28.31 150.5,28.31 149.61,27.42 149.61,18.66
N31208551 on TOP: 184.66,101.59 185.67,102.61 185.67,107.05 178.18,107.05 178.18,101.84 178.44,101.59
N31208551 on BOTTOM: 185.04,99.68 181.1,99.68 180.09,100.7 180.09,104.64 182.12,106.67 187.32,106.67 187.45,106.54 187.45,103.37 185.04,100.95
N31223527 on TOP: 186.94,120.77 184.78,120.77 184.53,121.02 184.53,124.2 183.13,124.2 182.88,124.45 182.88,124.96 183.13,125.21 184.53,125.21 184.53,127.12 188.59,127.12 188.59,123.05 186.94,123.05
N31730797 on BOTTOM: 188.98,76.82 188.98,74.28 192.28,70.98 192.28,68.06 192.91,67.43 196.98,67.43 197.48,67.93 197.48,75.81 197.1,76.19 195.33,76.19 194.44,77.08 189.23,77.08

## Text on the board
Ref Des/Assembly Bottom: B | H | C | A | E | G | F | BOTTOM ASSEMBLY | J721EX SOM 941x PMIC BOTTOM ASSEMBLY REV.E5
Ref Des/Silkscreen Bottom: P | N | H | SOM_CONN1 | SOM_CONN3 | SOM_CONN2 | FOR EVALUATION ONLY; | NOT FCC APPROVED FOR RESALE | SOM_CONN5 | SOM_CONN4
User.Comments: BOARD NAME: | J721EX SOM 941x PMIC BRD | REV: E5 | DATE: 03/06/2019 | DESCRIPTION: | SHEET | OF | 23 | TIDEP-01020 | SCALE: 1 | TEXAS INSTRUMENTS | CR_PMIC_2
Ref Des/Assembly Top: TOP ASSEMBLY | J721EX SOM 941x PMIC TOP ASSEMBLY REV.E5
Ref Des/Silkscreen Top: DGND | LPDDR4_DQ24 | PCIE0_TX | LPDDR4_DQ25 | CONN-SIDE | SOC-SIDE | LPDDR4_CA5 | P | N | LPDDR4-SIDE | PCIE0_RX | LPDDR4_DQ21 | VSYS_3V3 | ACC1 | J721EX SOM 941x PMIC BRD | PCB#: TIDEP-01020 | OPN# | TIDEP-01020 | ____ | ___
PAGE_OUTLINE: LAYOUT BY | REVIEWED BY | APPROVED BY | SIGNATURES | JA | AMB | ZA | DATE | 030619 | SIZE | SCALE: | D | NONE | SHEET 1 OF 23 | TIDEP-01020 | Rev | E5 | TEXAS INSTRUMENTS | J721EX SOM 941x PMIC BRD
DISPLAY_TOP: 2 | 15. | 16. | 17. | 19. | 18. | ALL UNCONNECTED VIA'S SHALL BE SUPPRESSED IN INTERNAL LAYERS. | NA | PCB SHALL BE MANUFACTURED USING I-SPEED OR EQUIVALENT. | ALL THE IMPEDANCE SHALL BE MATCHED AS PER IMPEDANCE TABLE WITH +/-10% TOLERANCE. | BACKDRILLING TO BE DONE FROM L16 TO L11. | BACKDRILLING TO BE DONE FROM L01 TO L10. | BACKDRILLING TO BE DONE FROM L16 TO L04. | VIA HOLES THAT HAVE MASK OPEN SHALL BE FILLED WITH NON CONDUCTIVE INK AND CAP PLATED, | DETAIL-A
User.11: PROC079 TOP ASSEMBLY REV.E2
User.12: PROC079 TOP ASSEMBLY REV.E2
User.20: INNER-SIGNAL-6 | 17
User.21: GROUND-PLANE-06 | 18
User.22: INNER-SIGNAL-5 | 15
User.23: GROUND-PLANE-05 | 16
User.24: INNER-SIGNAL-4 | 13
User.27: INNER-SIGNAL-04 | 15
User.40: 17. | 18. | 19. | 12. | 13. | 14. | 15. | 16. | 02 | 03 | 04 | 05 | 06 | 07 | 08 | 09 | 10. | 11. | STRIPLINE | MICROSTRIP | EDGE COUPLED MICROSTRIP | EDGE COUPLED STRIPLINE | L1 | L16 | L1/L16 | L3,L5,L7, | L3,L5 | L3,L5,L10 | L10,L12,L14 | L7 | L12,L14 | L3 | 4.3 | 18 | 13 | 9 | 3 | 3.8 | 4.7 | 6.3 | 7.4 | 8 | 6 | 5 | 7.3 | NOT APPLICABLE | - | 5.4 | 15 | 5.6 | 5.7 | 5.8 | 100 | 90 | 80 | 66 | 33 | 40 | 85 | 50 | 132 | L2 | L2/L15 | L6/L8 | L2/L4 | L2/L4,L4/L6,L6/L8, | L9/L11,L11/L13,L13/L15 | L11/L13,L13/L15 | L2/L4,L4/L6,L9/L11 | L2/L4,L4/L6
User.41: 0.00400 | 0.00440 | 1oz. | 1.31oz | L15 | L16 | GROUND-PLANE-5 | INNER-SIGNAL-6 | INNER-SIGNAL-5 | GROUND-PLANE-6 | SECONDARY SIDE
